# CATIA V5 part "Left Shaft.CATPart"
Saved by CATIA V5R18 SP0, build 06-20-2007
Part number: Left hand shaft
Bounding box of the stored display mesh (mm): x 0 to 100, y -25 to 25, z -35 to 35
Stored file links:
  D:\Shriniwas\v5_r19\c16_CAT_v5r19\c16_Part\CV Joint\Left hand shaft.CATPart
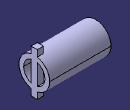
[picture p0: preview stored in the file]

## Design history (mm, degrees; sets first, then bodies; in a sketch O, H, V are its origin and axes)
Body1 (main body)
  Sketch1 on yz-plane, origin (0, 0, 0), H (0, 1, 0), V (0, 0, 1)
    circle A1 centre (0, 0) radius 25
    circle A2 centre (0, 0) radius 17.5
    radius A1 = 25
    radius A2 = 17.5
  Pad1: profile Sketch1, direction (1, 0, 0), length 100
  Sketch2 on end face of Pad1, origin (100, 0, 0), H (0, 1, 0), V (0, 0, 1)
    line L1 (5, 35) -> (5, -35)
    line L2 (5, -35) -> (-5, -35)
    line L3 (-5, -35) -> (-5, 35)
    line L4 (-5, 35) -> (5, 35)
    length L1 = 70
    length L4 = 10
    vertical: L1 V, L3 V
    horizontal: L2 H, L4 H
    equidistance: L1 L3 O, L2 L4 O
  Pad2: profile Sketch2, direction (-1, 0, 0), length 10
